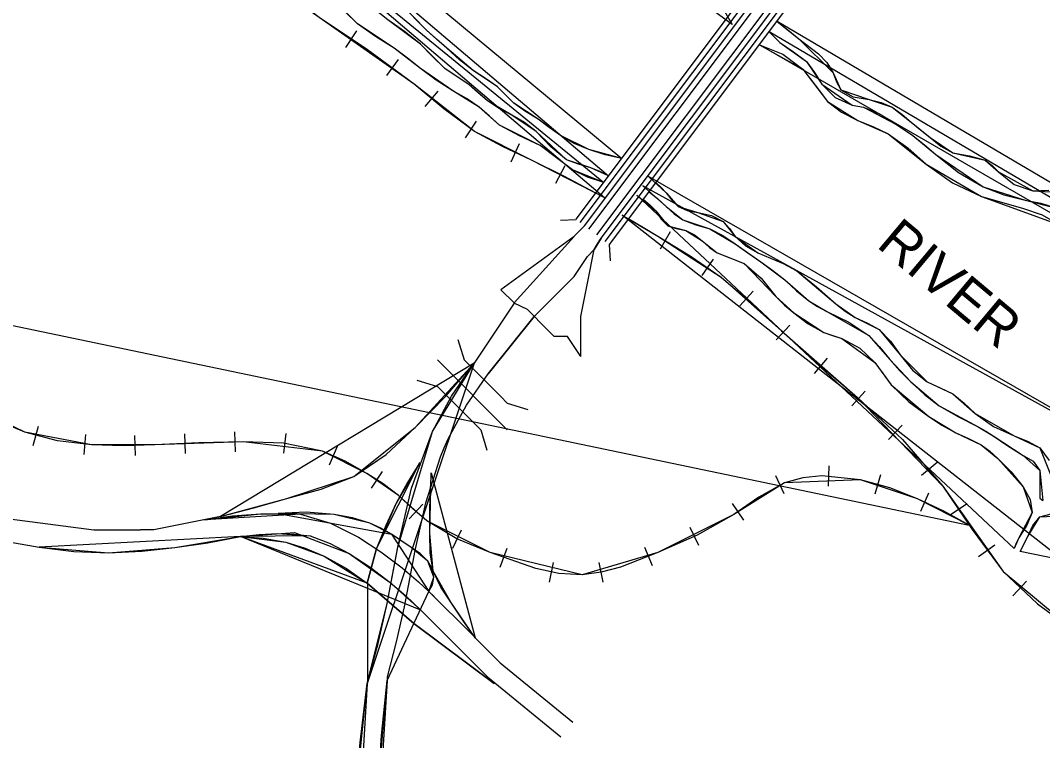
# Model space of a CAD drawing. Extents: x 5.01 to 9.58, y 0.27 to 3.39.
# Drawn here: x 8.36 to 8.957, y 2.595 to 3.015 of the extents above; entities that cross this region are included whole.
import ezdxf

# ---------------------------------------------------------------- set-up
doc = ezdxf.new("R2010")
doc.units = 0
doc.layers.add('MO_001_NOSHOW', color=7, linetype='Continuous')
doc.layers.add('MO_001_VIEW_PV', color=7, linetype='Continuous')

msp = doc.modelspace()

# ---------------------------------------------------------------- linework, layer by layer
at = {"layer": 'MO_001_NOSHOW'}
for points in [[(8.70157, 2.9117), (8.65869, 2.93369), (8.62541, 2.95034), (8.59027, 2.97807), (8.5348, 3.0169), (8.49598, 3.04649), (8.4368, 3.10566), (8.41461, 3.12785), (8.36468, 3.17778), (8.31291, 3.22585), (8.25559, 3.28687), (8.24264, 3.30537), (8.20011, 3.3442), (8.14278, 3.38672)], [(8.776, 3.01295), (8.76004, 3.02456), (8.74117, 3.03617), (8.72666, 3.04634), (8.70635, 3.05939), (8.69909, 3.0681), (8.69329, 3.08696), (8.68893, 3.10292), (8.67877, 3.11599), (8.65266, 3.1392), (8.6454, 3.14501), (8.62074, 3.16242), (8.60331, 3.17402), (8.583, 3.18999), (8.56269, 3.20595), (8.55108, 3.22627), (8.54528, 3.25093), (8.54817, 3.27271), (8.55544, 3.29157), (8.56559, 3.30753), (8.59171, 3.3322)], [(8.70383, 2.92445), (8.69341, 2.92911), (8.6792, 2.93384), (8.66143, 2.95043), (8.64722, 2.95991), (8.63299, 2.9682), (8.62233, 2.97768), (8.60812, 2.98716), (8.5939, 3.00137), (8.57494, 3.01559), (8.55717, 3.0298), (8.53466, 3.04403), (8.51808, 3.05706), (8.50505, 3.06654), (8.48964, 3.08075), (8.46831, 3.09971), (8.45528, 3.11748), (8.43751, 3.12933), (8.42803, 3.15539), (8.41856, 3.16014), (8.41263, 3.16487), (8.40552, 3.17553), (8.39605, 3.18501), (8.39012, 3.19093)], [(8.71146, 2.93463), (8.69223, 2.93977), (8.67565, 2.94806), (8.66262, 2.95754), (8.6484, 2.96701), (8.63891, 2.9765), (8.6247, 2.98597), (8.6093, 2.99901), (8.59745, 3.00966), (8.58205, 3.02507), (8.56428, 3.03811), (8.55362, 3.04403), (8.53348, 3.0535), (8.51334, 3.06654), (8.49674, 3.07839), (8.47187, 3.1009), (8.46239, 3.12222), (8.45766, 3.12814), (8.44935, 3.13762), (8.43988, 3.15539), (8.42921, 3.17079), (8.41619, 3.1862), (8.40434, 3.18975)], [(8.70095, 2.92061), (8.68276, 2.92791), (8.6638, 2.94214), (8.64011, 2.95398), (8.62826, 2.96465), (8.61286, 2.97412), (8.5939, 2.98716), (8.57849, 2.99901), (8.55717, 3.01322), (8.54295, 3.02744), (8.52281, 3.04284), (8.50385, 3.05706), (8.48253, 3.07719), (8.46831, 3.09379), (8.44699, 3.11629), (8.42803, 3.13881), (8.41027, 3.15539), (8.38538, 3.17672), (8.37591, 3.1862)], [(8.79194, 3.00101), (8.8172, 2.98684), (8.83163, 2.96797), (8.8494, 2.95686), (8.86716, 2.94908), (8.88938, 2.93132), (8.92157, 2.91244), (8.96711, 2.89578), (8.98155, 2.88023), (9.00264, 2.86247), (9.02818, 2.85358), (9.05151, 2.83471), (9.07038, 2.82916), (9.09814, 2.81583), (9.12368, 2.79251), (9.15255, 2.77697), (9.18475, 2.75697), (9.20475, 2.74809), (9.24361, 2.74032)], [(8.72028, 2.91324), (8.73132, 2.90397), (8.73833, 2.8952), (8.74885, 2.89258), (8.75848, 2.88644), (8.76725, 2.87944), (8.78302, 2.87329), (8.80142, 2.85402), (8.81193, 2.84439), (8.82946, 2.833), (8.83997, 2.82949), (8.85925, 2.81547), (8.86889, 2.80232), (8.89079, 2.78393), (8.90657, 2.77428), (8.92147, 2.76728), (8.9311, 2.7594), (8.946, 2.74274), (8.95125, 2.72786), (8.94336, 2.71296), (8.94074, 2.70682)], [(8.71169, 2.90157), (8.73266, 2.88931), (8.76964, 2.86527), (8.80478, 2.83384), (8.84915, 2.79501), (8.89908, 2.74323), (8.93421, 2.6933), (8.97674, 2.65818), (9.02851, 2.62304), (9.08029, 2.5879), (9.12836, 2.56571), (9.16534, 2.53428), (9.21157, 2.51025)], [(8.68368, 2.88914), (8.68973, 2.89526)], [(8.69538, 2.88135), (8.6994, 2.88802)], [(8.63338, 2.80891), (8.66029, 2.84238)], [(8.47708, 2.72543), (8.5159, 2.73593), (8.55505, 2.74883), (8.59088, 2.77751), (8.62521, 2.81508)], [(8.56284, 2.62798), (8.57453, 2.67475), (8.5807, 2.70758), (8.60085, 2.77514), (8.62521, 2.81508)], [(8.5935, 2.75701), (8.57973, 2.73334), (8.56827, 2.70671)], [(8.62585, 2.65462), (8.61163, 2.67545), (8.60135, 2.69347), (8.59942, 2.71563), (8.60022, 2.75107)], [(8.46771, 2.72355), (8.50046, 2.72711), (8.52398, 2.72678)], [(8.57698, 2.71524), (8.56437, 2.72153), (8.5435, 2.72665), (8.51083, 2.72726)], [(8.94424, 2.70507), (8.94862, 2.71383), (8.95563, 2.72522), (8.9714, 2.7261), (8.99419, 2.71821), (9.01171, 2.70595), (9.00995, 2.70069), (9.02134, 2.68667), (9.03536, 2.68492), (9.06516, 2.68755), (9.08707, 2.67966), (9.10634, 2.67265), (9.12912, 2.66476), (9.15015, 2.65513), (9.16593, 2.65951)], [(8.37113, 2.70759), (8.4117, 2.70429), (8.4504, 2.70732), (8.48878, 2.71374)], [(8.48878, 2.71374), (8.52038, 2.71615), (8.55218, 2.70389), (8.57616, 2.68688), (8.59404, 2.67086)], [(8.48878, 2.71374), (8.51055, 2.71546), (8.52943, 2.71415)], [(8.48878, 2.71374), (8.51526, 2.71041), (8.53764, 2.70222), (8.56284, 2.68645)], [(8.5988, 2.68166), (8.60179, 2.69002), (8.59824, 2.69947), (8.5884, 2.70736), (8.57698, 2.71524)], [(8.56284, 2.68645), (8.56827, 2.70671)], [(8.56284, 2.68645), (8.59013, 2.66307)], [(8.59013, 2.66307), (8.6369, 2.62798)], [(8.55114, 2.42918), (8.55295, 2.48266), (8.55578, 2.55874), (8.56284, 2.62798)], [(8.56284, 2.44087), (8.56674, 2.49545), (8.56892, 2.56531), (8.57454, 2.62961)]]:
    msp.add_lwpolyline(points, close=True, dxfattribs=at)
for points in [[(9.24694, 2.75253), (8.8022, 3.0147), (8.81498, 3.0046), (8.83496, 2.98462), (8.83941, 2.97462), (8.85607, 2.96907), (8.86939, 2.96462), (8.88049, 2.95575), (8.89159, 2.94686), (8.90492, 2.93799), (8.92379, 2.93354), (8.93157, 2.92688), (8.95157, 2.91577), (8.96933, 2.91466)], [(9.23806, 2.7492), (8.79768, 3.00866), (8.80387, 3.00238), (8.81942, 2.99128), (8.82831, 2.97795), (8.84607, 2.96573), (8.85274, 2.96462), (8.87161, 2.95464), (8.88161, 2.94797), (8.89492, 2.93686), (8.9227, 2.91799), (8.94712, 2.91022), (8.96489, 2.90577)], [(7.7064, 2.97253), (8.91442, 2.72047), (8.88428, 2.73584), (8.851, 2.74694), (8.80662, 2.74508), (8.77704, 2.72659), (8.73266, 2.7044), (8.68828, 2.69146), (8.63465, 2.7044), (8.59767, 2.72289), (8.58103, 2.73768), (8.56253, 2.75063), (8.53665, 2.76358), (8.49042, 2.76913), (8.43865, 2.76727), (8.40167, 2.76727), (8.36283, 2.77467), (8.31661, 2.79686)], [(9.16329, 2.67353), (8.72717, 2.92407), (8.73745, 2.91448), (8.74446, 2.9066), (8.75586, 2.90309), (8.77076, 2.89784), (8.77776, 2.88907), (8.7909, 2.87944), (8.8058, 2.87329), (8.81369, 2.86892), (8.83647, 2.84964), (8.84786, 2.84175), (8.86188, 2.83474), (8.87415, 2.81986), (8.88992, 2.80408), (8.90481, 2.79707), (8.91795, 2.78568), (8.94074, 2.77254), (8.95563, 2.76553), (8.96264, 2.748)], [(9.17644, 2.66914), (8.72372, 2.91866), (8.73745, 2.9066), (8.74709, 2.89871), (8.76287, 2.89345), (8.77776, 2.88469), (8.79266, 2.87417), (8.80668, 2.86366), (8.8207, 2.8514), (8.83121, 2.84526), (8.85575, 2.83124), (8.86802, 2.81722), (8.88028, 2.80408), (8.89692, 2.79006), (8.91971, 2.77779), (8.92846, 2.77254), (8.946, 2.76114), (8.95563, 2.75239), (8.95738, 2.73487)]]:
    msp.add_lwpolyline(points, dxfattribs=at)
at = {"layer": 'MO_001_VIEW_PV'}
for p, q in [((8.68478, 2.89908), (8.8548, 3.12577)), ((8.68724, 2.8972), (8.85726, 3.12389)), ((8.68971, 2.89531), (8.85972, 3.122)), ((8.69217, 2.89342), (8.86219, 3.12011)), ((8.69696, 2.88995), (8.86697, 3.11664)), ((8.69942, 2.88807), (8.86943, 3.11476)), ((8.70189, 2.88618), (8.87189, 3.11287)), ((8.70435, 2.8843), (8.87437, 3.11098)), ((8.55028, 2.99953), (8.5568, 3.00924)), ((8.57419, 2.983), (8.581, 2.99242)), ((8.59666, 2.96503), (8.60419, 2.97401)), ((8.62029, 2.94662), (8.62666, 2.95648)), ((8.64695, 2.93271), (8.65174, 2.94329)), ((8.67304, 2.9201), (8.6784, 2.93054)), ((8.67565, 2.89851), (8.68478, 2.89893)), ((8.73985, 2.89184), (8.73392, 2.88169)), ((8.68362, 2.88908), (8.64087, 2.85792)), ((8.68362, 2.88908), (8.64855, 2.85024)), ((8.70492, 2.87488), (8.70435, 2.8843)), ((8.76493, 2.87589), (8.75826, 2.86632)), ((8.64855, 2.85024), (8.64087, 2.85792)), ((8.78827, 2.85719), (8.78044, 2.8485)), ((8.65637, 2.84633), (8.64855, 2.85009)), ((8.66029, 2.84241), (8.65637, 2.84633)), ((8.6642, 2.8385), (8.66029, 2.84241)), ((8.80973, 2.83719), (8.80175, 2.82865)), ((8.68754, 2.81893), (8.67986, 2.83067)), ((8.61564, 2.82893), (8.61941, 2.81704)), ((8.64463, 2.77617), (8.60377, 2.81704)), ((8.64087, 2.79559), (8.61941, 2.81704)), ((8.83146, 2.81806), (8.82393, 2.80908)), ((8.59188, 2.80517), (8.60377, 2.8014)), ((8.62521, 2.77994), (8.60377, 2.8014)), ((8.64463, 2.79168), (8.64087, 2.79559)), ((8.85364, 2.79879), (8.84596, 2.79008)), ((8.64463, 2.79168), (8.65667, 2.78806)), ((8.36765, 2.76704), (8.37084, 2.77834)), ((8.62912, 2.77617), (8.62521, 2.77994)), ((8.87538, 2.77878), (8.86726, 2.77052)), ((8.39751, 2.76168), (8.39852, 2.77342)), ((8.42737, 2.7611), (8.42708, 2.7727)), ((8.45664, 2.76226), (8.45622, 2.77386)), ((8.48578, 2.76327), (8.48549, 2.77487)), ((8.51419, 2.76241), (8.5155, 2.774)), ((8.62912, 2.77617), (8.63275, 2.76414)), ((8.54071, 2.75574), (8.54535, 2.76647)), ((8.83233, 2.74327), (8.83262, 2.75501)), ((8.89567, 2.75704), (8.88668, 2.74951)), ((8.56535, 2.74196), (8.57172, 2.75168)), ((8.80638, 2.73863), (8.80146, 2.74922)), ((8.85958, 2.73878), (8.86291, 2.74994)), ((8.88611, 2.72864), (8.89089, 2.73935)), ((8.58723, 2.72414), (8.59521, 2.7327)), ((8.78276, 2.72342), (8.77609, 2.73298)), ((8.91335, 2.73284), (8.90349, 2.72645)), ((8.6129, 2.70703), (8.61782, 2.71761)), ((8.75653, 2.70848), (8.75146, 2.71907)), ((8.64043, 2.69588), (8.64463, 2.7069)), ((8.72943, 2.69674), (8.72493, 2.70747)), ((8.92944, 2.70878), (8.91987, 2.70196)), ((8.66927, 2.68718), (8.67159, 2.69863)), ((8.70058, 2.68718), (8.69827, 2.69863)), ((8.94785, 2.68776), (8.93988, 2.67906)), ((8.56289, 2.68645), (8.56289, 2.62804)), ((8.57448, 2.62964), (8.59883, 2.68167)), ((8.59796, 2.68254), (8.62521, 2.65529)), ((8.57448, 2.63182), (8.57448, 2.62964))]:
    msp.add_line(p, q, dxfattribs=at)
for points in [[(8.69633, 2.91444), (8.67762, 2.92427), (8.65869, 2.93369), (8.64174, 2.94155), (8.62541, 2.95034), (8.6075, 2.96364), (8.59027, 2.97807), (8.56292, 2.99803), (8.5348, 3.0169), (8.51496, 3.03116), (8.49598, 3.04649), (8.46581, 3.07545), (8.4368, 3.10566), (8.42574, 3.11678), (8.41461, 3.12785), (8.38973, 3.15292), (8.36468, 3.17778), (8.36252, 3.17986), (8.36035, 3.18194)], [(8.70095, 2.92061), (8.69156, 2.92362), (8.68276, 2.92791), (8.6733, 2.93506), (8.6638, 2.94214), (8.65177, 2.94782), (8.64011, 2.95398), (8.63414, 2.95924), (8.62826, 2.96465), (8.62077, 2.96967), (8.61286, 2.97412), (8.60314, 2.98032), (8.5939, 2.98716), (8.58629, 2.9932), (8.57849, 2.99901), (8.56762, 3.00586), (8.55717, 3.01322), (8.54999, 3.02022)], [(8.70383, 2.92445), (8.6987, 2.92695), (8.69341, 2.92911), (8.68613, 2.93124), (8.6792, 2.93384), (8.66997, 2.94145), (8.66143, 2.95043), (8.65463, 2.95561), (8.64722, 2.95991), (8.63989, 2.96377), (8.63299, 2.9682), (8.62767, 2.97293), (8.62233, 2.97768), (8.61521, 2.98243), (8.60812, 2.98716), (8.60088, 2.99409), (8.5939, 3.00137), (8.58462, 3.00871), (8.57494, 3.01559)], [(8.71146, 2.93463), (8.70173, 2.93672), (8.69223, 2.93977), (8.68368, 2.94345), (8.67565, 2.94806), (8.66914, 2.9528), (8.66262, 2.95754), (8.65533, 2.96206), (8.6484, 2.96701), (8.64366, 2.97176), (8.63891, 2.9765), (8.63198, 2.98143), (8.6247, 2.98597), (8.6168, 2.99223), (8.6093, 2.99901), (8.60333, 3.0043), (8.59745, 3.00966), (8.58981, 3.01743)], [(8.8022, 3.0147), (8.8086, 3.00972), (8.81498, 3.0046), (8.82636, 2.99576), (8.83128, 2.99068), (8.83496, 2.98462), (8.83694, 2.97929), (8.83941, 2.97462), (8.84672, 2.97071), (8.85607, 2.96907), (8.8631, 2.9674), (8.86939, 2.96462), (8.87507, 2.96047), (8.88049, 2.95575), (8.88601, 2.95127), (8.89159, 2.94686), (8.89795, 2.94181), (8.90492, 2.93799), (8.91459, 2.93607), (8.92379, 2.93354), (8.92782, 2.93055), (8.93157, 2.92688), (8.94074, 2.91949), (8.95157, 2.91577), (8.96097, 2.91603)], [(8.79768, 3.00866), (8.80065, 3.00541), (8.80387, 3.00238), (8.8119, 2.99699), (8.81942, 2.99128), (8.82399, 2.98488), (8.82831, 2.97795), (8.83617, 2.97018), (8.84607, 2.96573), (8.84941, 2.96519), (8.85274, 2.96462), (8.8625, 2.96058), (8.87161, 2.95464), (8.87667, 2.95134), (8.88161, 2.94797), (8.88835, 2.94257), (8.89492, 2.93686), (8.90824, 2.92646), (8.9227, 2.91799), (8.93461, 2.91339), (8.94712, 2.91022), (8.9562, 2.90842), (8.96489, 2.90577)], [(8.79194, 3.00101), (8.80554, 2.99545), (8.8172, 2.98684), (8.82439, 2.97735), (8.83163, 2.96797), (8.83989, 2.9616), (8.8494, 2.95686), (8.85848, 2.95319), (8.86716, 2.94908), (8.87857, 2.94077), (8.88938, 2.93132), (8.90462, 2.92044), (8.92157, 2.91244), (8.94554, 2.90568), (8.95698, 2.90169), (8.96711, 2.89578)], [(8.7315, 2.92043), (8.73459, 2.91759), (8.73745, 2.91448), (8.74079, 2.91024), (8.74446, 2.9066), (8.74978, 2.90427), (8.75586, 2.90309), (8.76393, 2.90136), (8.77076, 2.89784), (8.77437, 2.89367), (8.77776, 2.88907), (8.78379, 2.88354), (8.7909, 2.87944), (8.79836, 2.87635), (8.8058, 2.87329), (8.80982, 2.87126), (8.81369, 2.86892), (8.82533, 2.85964), (8.83647, 2.84964), (8.84194, 2.84539), (8.84786, 2.84175), (8.85508, 2.83846), (8.86188, 2.83474), (8.86849, 2.82796), (8.87415, 2.81986), (8.88128, 2.81097), (8.88992, 2.80408), (8.89741, 2.80064), (8.90481, 2.79707), (8.91158, 2.79168), (8.91795, 2.78568), (8.92868, 2.77815), (8.94074, 2.77254), (8.94859, 2.76953), (8.95563, 2.76553), (8.9612, 2.75823)], [(8.7276, 2.91522), (8.73255, 2.91097), (8.73745, 2.9066), (8.7421, 2.90232), (8.74709, 2.89871), (8.75481, 2.89583), (8.76287, 2.89345), (8.77058, 2.88957), (8.77776, 2.88469), (8.78522, 2.87941), (8.79266, 2.87417), (8.7998, 2.86909), (8.80668, 2.86366), (8.81358, 2.85736), (8.8207, 2.8514), (8.82581, 2.84813), (8.83121, 2.84526), (8.84406, 2.83897), (8.85575, 2.83124), (8.8621, 2.82451), (8.86802, 2.81722), (8.87398, 2.81049), (8.88028, 2.80408), (8.88829, 2.79666), (8.89692, 2.79006), (8.90816, 2.78371), (8.91971, 2.77779), (8.92415, 2.77525), (8.92846, 2.77254), (8.93702, 2.76668), (8.946, 2.76114), (8.9518, 2.75781), (8.95563, 2.75239), (8.95579, 2.74063), (8.9558, 2.7361), (8.95738, 2.73487)], [(8.72414, 2.91061), (8.72797, 2.90758), (8.73132, 2.90397), (8.73457, 2.89912), (8.73833, 2.8952), (8.74335, 2.89363), (8.74885, 2.89258), (8.75397, 2.89007), (8.75848, 2.88644), (8.76272, 2.88267), (8.76725, 2.87944), (8.77514, 2.87632), (8.78302, 2.87329), (8.79284, 2.86464), (8.80142, 2.85402), (8.80649, 2.849), (8.81193, 2.84439), (8.82032, 2.83799), (8.82946, 2.833), (8.83469, 2.83123), (8.83997, 2.82949), (8.8505, 2.82373), (8.85925, 2.81547), (8.8641, 2.80888), (8.86889, 2.80232), (8.87911, 2.79242), (8.89079, 2.78393), (8.89852, 2.77878), (8.90657, 2.77428), (8.91413, 2.77098), (8.92147, 2.76728), (8.92646, 2.76358), (8.9311, 2.7594), (8.93892, 2.75162), (8.946, 2.74274), (8.95003, 2.73539), (8.95125, 2.72786), (8.94804, 2.72035), (8.94336, 2.71296), (8.94197, 2.70991), (8.94074, 2.70682)], [(8.71566, 2.89931), (8.72417, 2.89435), (8.73266, 2.88931), (8.75153, 2.87783), (8.76964, 2.86527), (8.78752, 2.84996), (8.80478, 2.83384), (8.82683, 2.8143), (8.84915, 2.79501), (8.87554, 2.77043), (8.89908, 2.74323), (8.91616, 2.7178), (8.93421, 2.6933), (8.95427, 2.67452), (8.97674, 2.65818)], [(8.68368, 2.88914), (8.68671, 2.8922), (8.68973, 2.89526)], [(8.69538, 2.88135), (8.69739, 2.88468), (8.6994, 2.88802)], [(8.66029, 2.84238), (8.66029, 2.84238), (8.67979, 2.86187), (8.68368, 2.86576), (8.69149, 2.87745), (8.69538, 2.88135)], [(8.68759, 2.81898), (8.68759, 2.82288), (8.68759, 2.83067), (8.68759, 2.84238), (8.69149, 2.86187), (8.69538, 2.88135)], [(7.04649, 2.69035), (7.08937, 2.69424), (7.12835, 2.69814), (7.2258, 2.70984), (7.28817, 2.71763), (7.33884, 2.72543), (7.36224, 2.72932), (7.4285, 2.74883), (7.45579, 2.75662), (7.50646, 2.78), (7.61561, 2.83067), (7.65069, 2.84238), (7.70137, 2.85407), (7.79102, 2.84628), (7.86507, 2.83067), (7.93525, 2.81898), (7.96254, 2.81119), (8.01711, 2.79559), (8.31338, 2.72932), (8.40302, 2.71763), (8.41472, 2.71763), (8.43031, 2.71763)], [(8.6486, 2.85017), (8.6486, 2.85017), (8.62521, 2.81508)], [(7.04649, 2.67866), (7.09327, 2.68255), (7.12835, 2.68645), (7.2531, 2.70205), (7.28817, 2.70593), (7.33884, 2.71374), (7.36613, 2.71763), (7.37782, 2.72153), (7.40511, 2.72932), (7.4168, 2.73322), (7.4324, 2.73712), (7.45969, 2.74491), (7.47917, 2.75662), (7.51036, 2.76831), (7.6234, 2.82288), (7.65069, 2.83067), (7.70137, 2.84238), (7.78713, 2.83457), (7.86507, 2.81898), (7.93525, 2.80729), (7.95864, 2.7995), (8.01321, 2.7839), (8.31338, 2.71763), (8.37113, 2.70759)], [(8.63338, 2.80891), (8.64684, 2.82564), (8.66029, 2.84238)], [(8.67979, 2.83067), (8.67199, 2.83067), (8.66419, 2.83847)], [(8.47708, 2.72543), (8.49648, 2.73056), (8.5159, 2.73593), (8.53597, 2.74136), (8.55505, 2.74883), (8.57387, 2.7617), (8.59088, 2.77751), (8.60872, 2.7958), (8.62521, 2.81508)], [(8.56284, 2.62798), (8.56915, 2.65125), (8.57453, 2.67475), (8.57765, 2.69115), (8.5807, 2.70758), (8.58873, 2.74204), (8.60085, 2.77514), (8.61196, 2.79575), (8.62521, 2.81508)], [(8.60566, 2.76034), (8.60781, 2.76561), (8.61013, 2.77082), (8.62074, 2.79047), (8.63338, 2.80891)], [(8.91442, 2.72047), (8.8996, 2.72866), (8.88428, 2.73584), (8.868, 2.74222), (8.851, 2.74694), (8.82837, 2.74917), (8.81721, 2.74807), (8.80662, 2.74508), (8.79147, 2.73668), (8.77704, 2.72659), (8.75547, 2.71451), (8.73266, 2.7044), (8.71068, 2.6959), (8.69951, 2.69291), (8.68828, 2.69146), (8.67482, 2.69218), (8.66136, 2.69507), (8.63465, 2.7044), (8.61524, 2.71242), (8.59767, 2.72289), (8.58931, 2.73018), (8.58103, 2.73768), (8.57204, 2.7445), (8.56253, 2.75063), (8.54989, 2.75784), (8.53665, 2.76358), (8.51395, 2.76825), (8.49042, 2.76913), (8.46445, 2.76843), (8.43865, 2.76727), (8.42018, 2.76676), (8.40167, 2.76727), (8.38198, 2.76976), (8.36283, 2.77467), (8.33928, 2.78468)], [(8.57459, 2.63189), (8.57994, 2.65222), (8.58456, 2.67271), (8.5877, 2.68915), (8.59074, 2.70563), (8.59696, 2.73337), (8.60566, 2.76034)], [(8.5935, 2.75701), (8.58627, 2.74538), (8.57973, 2.73334), (8.57359, 2.7202), (8.56827, 2.70671)], [(8.62585, 2.65462), (8.61865, 2.66492), (8.61163, 2.67545), (8.60579, 2.68422), (8.60135, 2.69347), (8.59952, 2.70431), (8.59942, 2.71563), (8.59945, 2.7294), (8.59969, 2.74302)], [(8.47708, 2.72543), (8.4381, 2.71763), (8.43031, 2.71763)], [(8.46771, 2.72355), (8.48402, 2.72591), (8.50046, 2.72711), (8.51223, 2.72725), (8.52398, 2.72678)], [(8.57698, 2.71524), (8.57082, 2.71866), (8.56437, 2.72153), (8.55411, 2.72469), (8.5435, 2.72665), (8.52716, 2.72798), (8.51083, 2.72726)], [(8.52388, 2.72681), (8.54139, 2.72165), (8.5578, 2.71342), (8.57085, 2.7049), (8.58316, 2.69545), (8.59269, 2.68731), (8.60183, 2.67871)], [(8.94424, 2.70507), (8.9464, 2.70941), (8.94862, 2.71383), (8.95159, 2.72022), (8.95563, 2.72522), (8.96302, 2.72714)], [(8.37113, 2.70759), (8.39134, 2.70508), (8.4117, 2.70429), (8.43109, 2.70522), (8.4504, 2.70732), (8.46967, 2.71015), (8.48878, 2.71374)], [(8.48878, 2.71374), (8.49962, 2.71502), (8.51055, 2.71546), (8.52001, 2.71512), (8.52943, 2.71415)], [(8.48878, 2.71374), (8.50212, 2.71286), (8.51526, 2.71041), (8.52665, 2.70689), (8.53764, 2.70222), (8.55069, 2.69503), (8.56284, 2.68645)], [(8.52943, 2.71415), (8.5411, 2.70973), (8.55218, 2.70389), (8.56451, 2.69582), (8.57616, 2.68688), (8.58529, 2.67908), (8.59404, 2.67086)], [(8.5988, 2.68166), (8.60091, 2.68563), (8.60179, 2.69002), (8.60084, 2.69502), (8.59824, 2.69947), (8.59365, 2.70379), (8.5884, 2.70736), (8.5827, 2.71134), (8.57698, 2.71524)], [(8.56284, 2.68645), (8.56556, 2.69658), (8.56827, 2.70671)], [(8.56284, 2.68645), (8.57648, 2.67476), (8.59013, 2.66307)], [(8.59404, 2.67086), (8.633, 2.63187), (8.67589, 2.59679)], [(8.59013, 2.66307), (8.61352, 2.64552), (8.6369, 2.62798)], [(8.62521, 2.65526), (8.64041, 2.64005), (8.68287, 2.60533)], [(8.55114, 2.42918), (8.55207, 2.45591), (8.55295, 2.48266), (8.55403, 2.52071), (8.55578, 2.55874), (8.55872, 2.59341), (8.56284, 2.62798)], [(8.56657, 2.49184), (8.56666, 2.49365), (8.56674, 2.49545), (8.56779, 2.53038), (8.56892, 2.56531), (8.57121, 2.59751), (8.57454, 2.62961)]]:
    msp.add_lwpolyline(points, dxfattribs=at)

# ---------------------------------------------------------------- texts
msp.add_text('RIVER', height=0.023189, rotation=320, dxfattribs=at).set_placement((8.85964, 2.88338))

doc.saveas('drawing.dxf')
